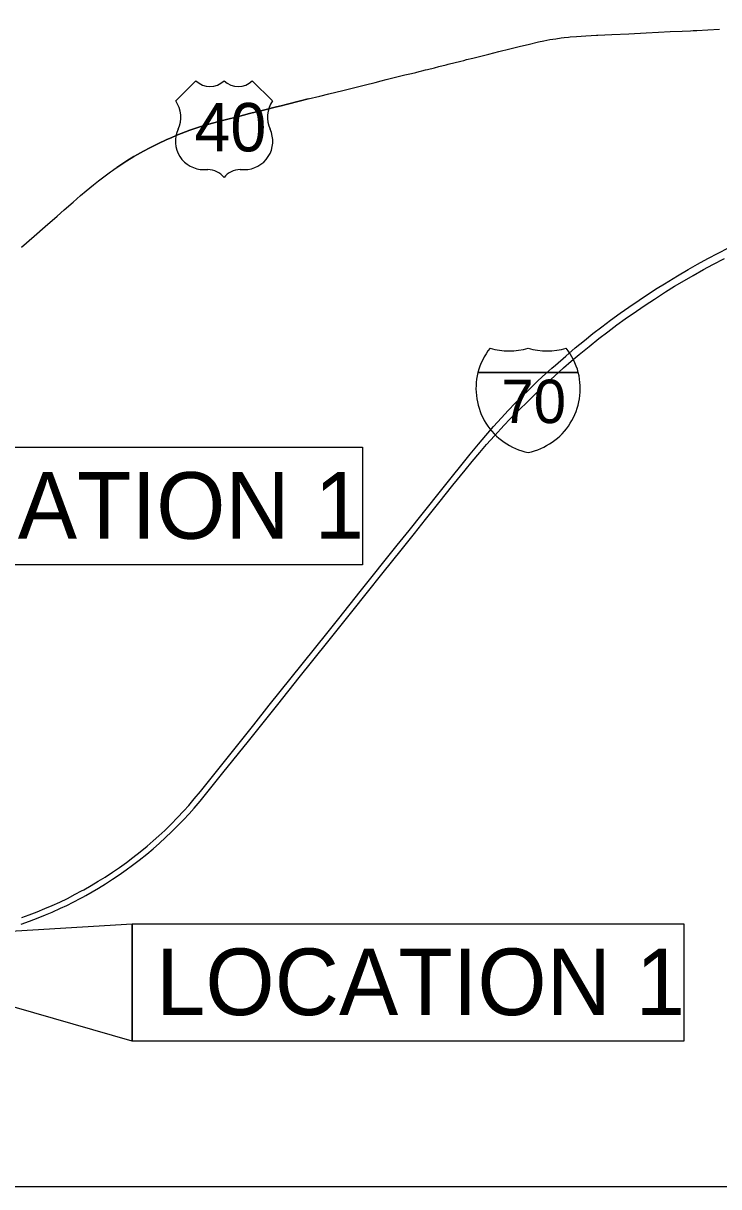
# Model space of a CAD drawing. Extents: x -29.6 to 34, y 0 to 22.
# Drawn here: x -19.868 to -18.092, y 1.053 to 4.023 of the extents above; entities that cross this region are included whole.
import ezdxf

# ---------------------------------------------------------------- set-up
doc = ezdxf.new("R2010")
doc.units = 0
for name, color, linetype in [('BR_P_Gen_Text', 7, 'Continuous'), ('GM_X_Interstate_Route', 7, 'Continuous'), ('GM_X_Interstate_Shield', 7, 'Continuous'), ('GM_X_Township_Road', 7, 'Continuous'), ('GM_X_US_Location', 7, 'Continuous'), ('GM_X_US_Route', 7, 'Continuous'), ('GM_X_US_Shield', 7, 'Continuous'), ('SH_Text', 7, 'Continuous')]:
    doc.layers.add(name, color=color, linetype=linetype)

msp = doc.modelspace()

# ---------------------------------------------------------------- linework, layer by layer
at = {"layer": 'BR_P_Gen_Text'}
for points in [[(-20.4101, 2.9402), (-19.0014, 2.9402), (-19.0014, 2.64), (-20.4101, 2.64)], [(-19.5899, 1.7242), (-19.5899, 1.424), (-20.4505, 1.6719)], [(-19.5899, 1.7242), (-18.1811, 1.7242), (-18.1811, 1.424), (-19.5899, 1.424)]]:
    msp.add_lwpolyline(points, close=True, dxfattribs=at)
at = {"layer": 'GM_X_Interstate_Route'}
for points in [[(-19.8719, 1.7401), (-19.8527, 1.7469), (-19.8325, 1.7546), (-19.8125, 1.7627), (-19.7943, 1.7705), (-19.7747, 1.7795), (-19.7553, 1.7889), (-19.735, 1.7993), (-19.7188, 1.8081), (-19.7135, 1.8109), (-19.6942, 1.8218), (-19.6762, 1.8325), (-19.6588, 1.8433), (-19.6398, 1.8557), (-19.622, 1.8679), (-19.604, 1.8808), (-19.5877, 1.8931), (-19.5694, 1.9076), (-19.5514, 1.9224), (-19.5363, 1.9353), (-19.5216, 1.9485), (-19.5067, 1.9625), (-19.4895, 1.9791), (-19.4744, 1.9945), (-19.4576, 2.0124), (-19.4452, 2.0263), (-19.4311, 2.0426), (-19.4156, 2.0615), (-19.3542, 2.1385), (-19.2794, 2.2316), (-19.2395, 2.2817), (-19.1834, 2.3518), (-19.0926, 2.4649), (-19.0618, 2.5036), (-19.0072, 2.5719), (-18.9126, 2.6901), (-18.882, 2.7283), (-18.8493, 2.7693), (-18.7952, 2.8371), (-18.7262, 2.9229), (-18.7056, 2.9481), (-18.6868, 2.9703), (-18.6669, 2.9931), (-18.6467, 3.0156), (-18.6297, 3.034), (-18.612, 3.0525), (-18.5944, 3.0703), (-18.576, 3.0882), (-18.5533, 3.1099), (-18.5332, 3.1285), (-18.518, 3.1421), (-18.5088, 3.1501), (-18.4824, 3.1731), (-18.458, 3.1938), (-18.4347, 3.2131), (-18.4129, 3.2305), (-18.3903, 3.248), (-18.3684, 3.2644), (-18.3434, 3.2825), (-18.3215, 3.298), (-18.2951, 3.3161), (-18.2714, 3.3319), (-18.2489, 3.3464), (-18.2306, 3.3578), (-18.1967, 3.3783), (-18.1701, 3.3939), (-18.1463, 3.4074), (-18.1192, 3.4222), (-18.0935, 3.4357), (-18.067, 3.4491)], [(-19.8736, 1.7232), (-19.8522, 1.7307), (-19.8299, 1.7391), (-19.811, 1.7467), (-19.7939, 1.754), (-19.7726, 1.7635), (-19.7568, 1.771), (-19.7401, 1.7793), (-19.7205, 1.7895), (-19.7154, 1.7923), (-19.7078, 1.7965), (-19.6981, 1.8019), (-19.6961, 1.803), (-19.6921, 1.8054), (-19.676, 1.8148), (-19.6577, 1.826), (-19.6396, 1.8377), (-19.6231, 1.8487), (-19.605, 1.8614), (-19.5886, 1.8734), (-19.5715, 1.8866), (-19.5524, 1.9018), (-19.5359, 1.9157), (-19.5202, 1.9295), (-19.5042, 1.944), (-19.489, 1.9584), (-19.4738, 1.9736), (-19.4588, 1.9891), (-19.4441, 2.0048), (-19.4314, 2.0192), (-19.4163, 2.0369), (-19.3953, 2.0626), (-19.3581, 2.1089), (-19.293, 2.1904), (-19.218, 2.2841), (-19.1634, 2.3523), (-19.0902, 2.4437), (-19.0256, 2.5248), (-18.9921, 2.5666), (-18.9491, 2.6203), (-18.9028, 2.678), (-18.869, 2.7203), (-18.8403, 2.7562), (-18.8064, 2.7985), (-18.7704, 2.8435), (-18.7395, 2.8822), (-18.7214, 2.9043), (-18.7022, 2.9269), (-18.6846, 2.9471), (-18.6643, 2.9696), (-18.6394, 2.9966), (-18.6249, 3.0118), (-18.6045, 3.0326), (-18.5768, 3.0601), (-18.5567, 3.0795), (-18.5377, 3.0976), (-18.5115, 3.1216), (-18.4881, 3.1427), (-18.4683, 3.1599), (-18.4478, 3.1772), (-18.423, 3.1975), (-18.3975, 3.2178), (-18.3749, 3.2352), (-18.3516, 3.2527), (-18.3303, 3.2681), (-18.3017, 3.2881), (-18.28, 3.3028), (-18.2561, 3.3185), (-18.2277, 3.3367), (-18.2044, 3.3512), (-18.1789, 3.3664), (-18.1572, 3.3789), (-18.1302, 3.394), (-18.1067, 3.4068), (-18.0773, 3.4222)]]:
    msp.add_lwpolyline(points, dxfattribs=at)
at = {"layer": 'GM_X_Interstate_Shield'}
for p, q in [((-18.7066, 3.131), (-18.4504, 3.131)), ((-18.4504, 3.131), (-18.7066, 3.131)), ((-18.4504, 3.131), (-18.7066, 3.131))]:
    msp.add_line(p, q, dxfattribs=at)
for centre, start, end in [((-18.5452, 3.0902), 141.669, 165.8066), ((-18.6272, 3.3526), 253.0091, 286.9909), ((-18.5299, 3.3526), 253.0091, 286.9909), ((-18.6118, 3.0902), 14.1934, 38.331), ((-18.5452, 3.0902), 165.8066, 258.463), ((-18.6118, 3.0902), 281.537, 14.1934)]:
    msp.add_arc(centre, 0.1665, start, end, dxfattribs=at)
at = {"layer": 'GM_X_Township_Road'}
for points in [[(-19.14, 3.8295), (-19.1599, 3.8245), (-19.1965, 3.8152), (-19.2096, 3.812), (-19.2214, 3.809), (-19.2509, 3.8016), (-19.2899, 3.792), (-19.3209, 3.7841), (-19.3492, 3.7772)], [(-19.3492, 3.7772), (-19.3526, 3.7763), (-19.3717, 3.7714), (-19.3942, 3.7651), (-19.4165, 3.7584), (-19.4275, 3.7547), (-19.4423, 3.7494), (-19.4754, 3.7367), (-19.4905, 3.7306), (-19.5012, 3.7259), (-19.5238, 3.7152), (-19.5446, 3.7047), (-19.5611, 3.6962), (-19.5764, 3.6878), (-19.5854, 3.6826), (-19.6032, 3.6715), (-19.6291, 3.6545)]]:
    msp.add_lwpolyline(points, dxfattribs=at)
at = {"layer": 'GM_X_US_Route'}
for points in [[(-19.14, 3.8295), (-19.1105, 3.8369), (-19.0876, 3.8425), (-19.052, 3.8512), (-19.0146, 3.8605), (-18.9936, 3.8658), (-18.9693, 3.8719), (-18.9535, 3.8759), (-18.9412, 3.8789), (-18.9207, 3.8841), (-18.8932, 3.8907), (-18.8764, 3.8947), (-18.865, 3.8974), (-18.8565, 3.8995), (-18.8498, 3.9011), (-18.8409, 3.9034), (-18.8353, 3.9048), (-18.8179, 3.9091), (-18.8066, 3.912), (-18.7957, 3.9148), (-18.7908, 3.916), (-18.788, 3.9167), (-18.7824, 3.9182), (-18.7502, 3.9262), (-18.7429, 3.928), (-18.7355, 3.9298), (-18.7194, 3.9337), (-18.696, 3.9396), (-18.6787, 3.9438), (-18.6536, 3.9502), (-18.6253, 3.9571), (-18.5976, 3.964), (-18.5784, 3.9687), (-18.5521, 3.975), (-18.5387, 3.9779), (-18.5229, 3.9809), (-18.5078, 3.9833), (-18.4942, 3.9852), (-18.4861, 3.9863), (-18.4758, 3.9873), (-18.4713, 3.9877), (-18.4546, 3.9892), (-18.4314, 3.9906), (-18.4035, 3.9919), (-18.4006, 3.9921), (-18.3645, 3.9939), (-18.3217, 3.9959), (-18.2773, 3.9981), (-18.2455, 3.9997), (-18.2161, 4.0013), (-18.1851, 4.0025), (-18.1638, 4.0035), (-18.1571, 4.0039), (-18.1478, 4.0044), (-18.1192, 4.0059), (-18.0895, 4.0073)], [(-19.3492, 3.7772), (-19.3209, 3.7841), (-19.2899, 3.792), (-19.2509, 3.8016), (-19.2214, 3.809), (-19.2096, 3.812), (-19.1965, 3.8152), (-19.1599, 3.8245), (-19.14, 3.8295)], [(-19.6291, 3.6545), (-19.6032, 3.6715), (-19.5854, 3.6826), (-19.5764, 3.6878), (-19.5611, 3.6962), (-19.5446, 3.7047), (-19.5238, 3.7152), (-19.5012, 3.7259), (-19.4905, 3.7306), (-19.4754, 3.7367), (-19.4423, 3.7494), (-19.4275, 3.7547), (-19.4165, 3.7584), (-19.3942, 3.7651), (-19.3717, 3.7714), (-19.3526, 3.7763), (-19.3492, 3.7772)], [(-19.8727, 3.451), (-19.8402, 3.4793), (-19.812, 3.5039), (-19.7815, 3.5305), (-19.7634, 3.5461), (-19.7406, 3.5661), (-19.7214, 3.5831), (-19.7072, 3.595), (-19.6883, 3.6106), (-19.6756, 3.6208), (-19.6589, 3.6335), (-19.6454, 3.6435), (-19.6402, 3.6471), (-19.6334, 3.6517), (-19.6291, 3.6545)]]:
    msp.add_lwpolyline(points, dxfattribs=at)
at = {"layer": 'GM_X_US_Shield'}
for p, q in [((-19.4271, 3.8759), (-19.4786, 3.8244)), ((-19.2314, 3.8244), (-19.2829, 3.8759)), ((-19.4065, 3.6493), (-19.3962, 3.6493)), ((-19.3138, 3.6493), (-19.3035, 3.6493))]:
    msp.add_line(p, q, dxfattribs=at)
for centre, radius, start, end in [((-19.391, 3.9127), 0.0515, 225.573, 314.427), ((-19.3189, 3.9127), 0.0515, 225.573, 314.427), ((-19.5376, 3.783), 0.0721, 334.5471, 35.0009), ((-19.1723, 3.783), 0.0721, 144.9991, 205.4529), ((-19.4073, 3.7214), 0.0721, 154.8319, 270.6383), ((-19.3027, 3.7214), 0.0721, 269.3617, 25.1681), ((-19.3962, 3.5978), 0.0515, 36.8699, 90), ((-19.3138, 3.5978), 0.0515, 90, 143.1301)]:
    msp.add_arc(centre, radius, start, end, dxfattribs=at)
at = {"layer": 'SH_Text'}
msp.add_lwpolyline([(-29.5833, 13.2079), (-10.7478, 13.2079), (-10.7478, 1.0528), (-29.5833, 1.0528)], close=True, dxfattribs=at)

# ---------------------------------------------------------------- texts
at = {"layer": 'BR_P_Gen_Text'}
for p in [(-20.3494, 2.7068), (-19.5291, 1.4908)]:
    msp.add_text('LOCATION 1', height=0.17, dxfattribs=at).set_placement(p)
at = {"layer": 'GM_X_Interstate_Shield'}
msp.add_text('70', height=0.11097, dxfattribs=at).set_placement((-18.6467, 3.002))
at = {"layer": 'GM_X_US_Location'}
for s in ['0', '/']:
    msp.add_text(s, height=0.000178, dxfattribs=at).set_placement((-18.6054, 3.9624))
at = {"layer": 'GM_X_US_Shield'}
msp.add_text('40', height=0.1236, dxfattribs=at).set_placement((-19.4308, 3.6956))

doc.saveas('drawing.dxf')
